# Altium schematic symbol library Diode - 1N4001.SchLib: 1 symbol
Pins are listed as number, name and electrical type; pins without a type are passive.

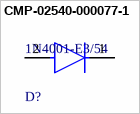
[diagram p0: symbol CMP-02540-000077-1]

## CMP-02540-000077-1
designator D?, comment 1N4001-E3/54
DIODE GEN PURP 50V 1A DO204AL; Max Surge Current: 30A; Forward Voltage: 1.1V; Capacitance: 15pF; Peak Non-Repetitive Surge Current: 45A; Polarity: Standard; Max Reverse Current: 5uA; Element Configuration: Single
footprint FP-1N4001-E3-54-MFG
pins: 1 C, 2 A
